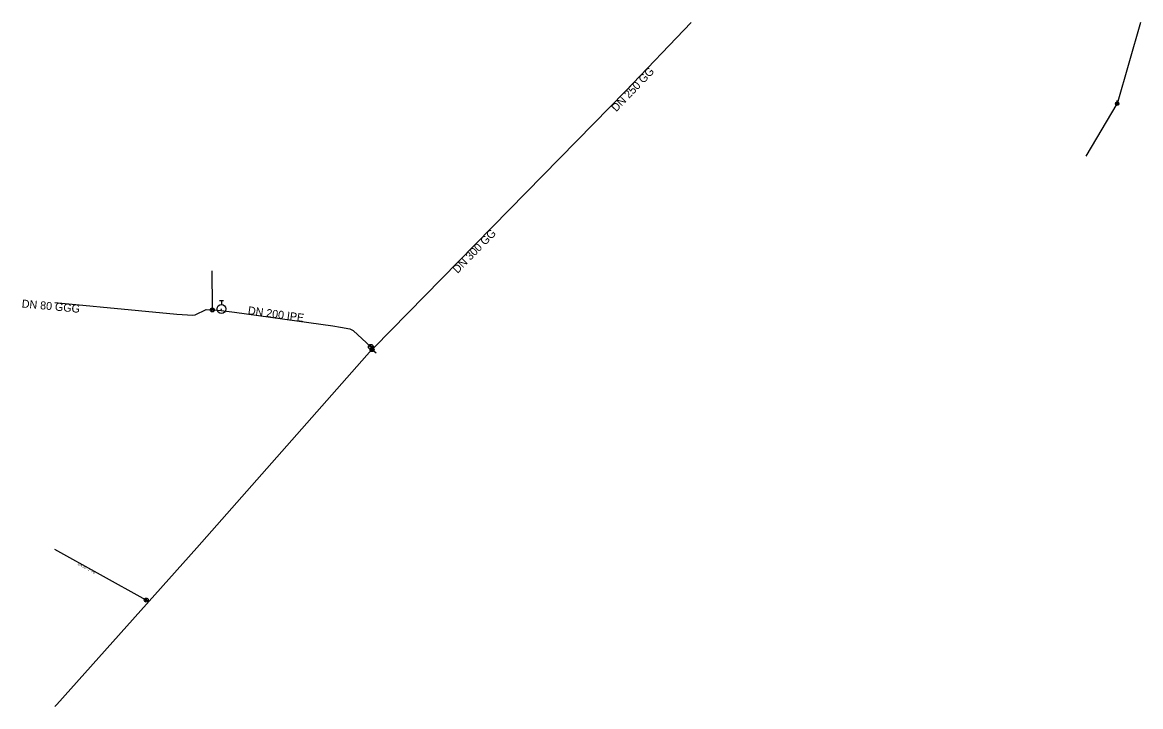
# Model space of a CAD drawing. Extents: x -466045 to -465821, y -1092725 to -1092588.
import ezdxf

# ---------------------------------------------------------------- set-up
doc = ezdxf.new("R2010")
doc.units = 0
for name, color, linetype in [('_hydrantova_odbocka_', 7, 'Continuous'), ('_pripojka_prevzato_z_dokumentace_', 7, 'Continuous'), ('_pripojka_priblizne_', 7, 'Continuous'), ('_voda_smvak_prevzato_z_dokumentace_', 7, 'Continuous'), ('_vodovodni_chranicka_', 7, 'Continuous'), ('Default', 7, 'Continuous'), ('MoLevel 27', 7, 'Continuous'), ('MoLevel 28', 7, 'Continuous'), ('MoLevel 30', 7, 'Continuous'), ('MoLevel 32', 7, 'Continuous'), ('MoLevel 42', 7, 'Continuous'), ('MoLevel 46', 7, 'Continuous'), ('MoLevel 53', 7, 'Continuous'), ('MoLevel 60', 7, 'Continuous')]:
    doc.layers.add(name, color=color, linetype=linetype)

# ---------------------------------------------------------------- blocks, each defined once
blk = doc.blocks.new('_uzaver_')
at = {"layer": 'Default'}
for p, q in [((-0.000035, -0.000035), (0.000035, 0.000035)), ((0.000035, -0.000035), (-0.000035, 0.000035))]:
    blk.add_line(p, q, dxfattribs=at)
for radius in [0.00005, 0.0000025]:
    blk.add_circle((0, 0), radius, dxfattribs=at)
blk = doc.blocks.new('_uzaver_pripojka_')
at = {"layer": 'Default'}
for p, q in [((-0.000035, -0.000035), (0.000035, 0.000035)), ((0.000035, -0.000035), (-0.000035, 0.000035))]:
    blk.add_line(p, q, dxfattribs=at)
for radius in [0.00005, 0.0000025]:
    blk.add_circle((0, 0), radius, dxfattribs=at)
blk = doc.blocks.new('_hydrant_voda_')
at = {"layer": 'Default'}
for p, q in [((-0.000023, 0.000095), (0.000023, 0.000095)), ((0, 0.000095), (0, 0.00005))]:
    blk.add_line(p, q, dxfattribs=at)
blk.add_circle((0, 0), 0.00005, dxfattribs=at)
blk = doc.blocks.new('_sachta_voda_')
at = {"layer": 'Default'}
blk.add_lwpolyline([(-0.00001, 0.000065), (0, 0.000035), (0.00001, 0.000065)], dxfattribs=at)
blk.add_circle((0, 0), 0.000035, dxfattribs=at)
blk = doc.blocks.new('_poklop_voda_')
at = {"layer": 'Default'}
blk.add_lwpolyline([(-0.00002, 0.00002), (0.00002, 0.00002), (0.00002, -0.00002), (-0.00002, -0.00002), (-0.00002, 0.00002)], dxfattribs=at)

msp = doc.modelspace()

# ---------------------------------------------------------------- linework, layer by layer
at = {"layer": '_hydrantova_odbocka_'}
msp.add_line((-466005.3, -1092645.76), (-466005.28, -1092645.45), dxfattribs=at)
at = {"layer": '_pripojka_prevzato_z_dokumentace_'}
msp.add_line((-466007.11, -1092645.64), (-466007.07, -1092645.07), dxfattribs=at)
msp.add_lwpolyline([(-465975.12, -1092653.58), (-465975.08, -1092653.6), (-465974.27, -1092654.27)], dxfattribs=at)
at = {"layer": '_pripojka_priblizne_'}
for p, q in [((-465821.02, -1092588.02), (-465825.74, -1092604.31)), ((-465831.97, -1092614.83), (-465825.74, -1092604.31)), ((-466007.07, -1092645.07), (-466007.15, -1092637.81))]:
    msp.add_line(p, q, dxfattribs=at)
msp.add_lwpolyline([(-466019.86, -1092704.08), (-466020.36, -1092703.78), (-466038.69, -1092693.67)], dxfattribs=at)
at = {"layer": '_voda_smvak_prevzato_z_dokumentace_'}
for p in [(-465930.71, -1092608.36), (-465975.33, -1092653.04)]:
    msp.add_line(p, (-465974.68, -1092653.19), dxfattribs=at)
for points in [[(-465911.1, -1092588.02), (-465924.31, -1092601.82), (-465930.71, -1092608.36)], [(-466038.69, -1092644.16), (-466021.91, -1092645.73), (-466014.21, -1092646.48), (-466010.99, -1092646.7), (-466010.56, -1092646.61), (-466008.34, -1092645.56), (-466007.11, -1092645.64), (-466005.3, -1092645.76)], [(-466005.3, -1092645.76), (-466002.69, -1092646.12), (-465982.94, -1092648.86), (-465981.43, -1092649.07), (-465979.55, -1092649.42), (-465978.9, -1092649.78), (-465975.33, -1092653.04)], [(-465974.68, -1092653.19), (-465975.12, -1092653.58), (-466010.23, -1092693.29), (-466038.28, -1092724.71), (-466038.69, -1092725.14)]]:
    msp.add_lwpolyline(points, dxfattribs=at)
at = {"layer": '_vodovodni_chranicka_'}
msp.add_line((-466002.69, -1092646.12), (-465982.94, -1092648.86), dxfattribs=at)

# ---------------------------------------------------------------- block references
at = {"layer": 'MoLevel 27', "xscale": 10000, "yscale": 10000, "rotation": 146.339791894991}
msp.add_blockref('_uzaver_', (-465975.33, -1092653.04), dxfattribs=at)
at = {"layer": 'MoLevel 28', "xscale": 17636.68430335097, "yscale": 17636.68430335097}
msp.add_blockref('_hydrant_voda_', (-466005.28, -1092645.45), dxfattribs=at)
at = {"layer": 'MoLevel 30', "xscale": 10000, "yscale": 10000}
msp.add_blockref('_sachta_voda_', (-465825.74, -1092604.31), dxfattribs=at)
at = {"layer": 'MoLevel 42', "xscale": 10000, "yscale": 10000}
msp.add_blockref('_poklop_voda_', (-465825.74, -1092604.31), dxfattribs=at)
msp.add_blockref('_poklop_voda_', (-465825.74, -1092604.31), dxfattribs=at)
at = {"layer": 'MoLevel 53', "xscale": 7999.999999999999, "yscale": 7999.999999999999}
for p in [(-466007.11, -1092645.64), (-466020.36, -1092703.78)]:
    msp.add_blockref('_uzaver_pripojka_', p, dxfattribs=at)
at = {"layer": 'MoLevel 53', "xscale": 8000, "yscale": 7999.999999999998, "rotation": 143.638725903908}
msp.add_blockref('_uzaver_pripojka_', (-465975.08, -1092653.6), dxfattribs=at)

# ---------------------------------------------------------------- texts
at = {"layer": 'MoLevel 32'}
msp.add_text("DN 25 - 1'' PE", height=0.455, rotation=331.1119, dxfattribs=at).set_placement((-466034.12, -1092696.71))
at = {"layer": 'MoLevel 46'}
for s, rotation, p in [('DN 250 GG', 46.2708, (-465926.14, -1092606.05)), ('DN 300 GG', 45.5592, (-465957.96, -1092638.43)), ('DN 80 GGG', 354.6368, (-466045.36, -1092645.14))]:
    msp.add_text(s, height=1.605, rotation=rotation, dxfattribs=at).set_placement(p)
at = {"layer": 'MoLevel 60'}
msp.add_text('DN 200 IPE', height=1.605, rotation=352.1076, dxfattribs=at).set_placement((-466000.05, -1092646.49))

doc.saveas('drawing.dxf')
